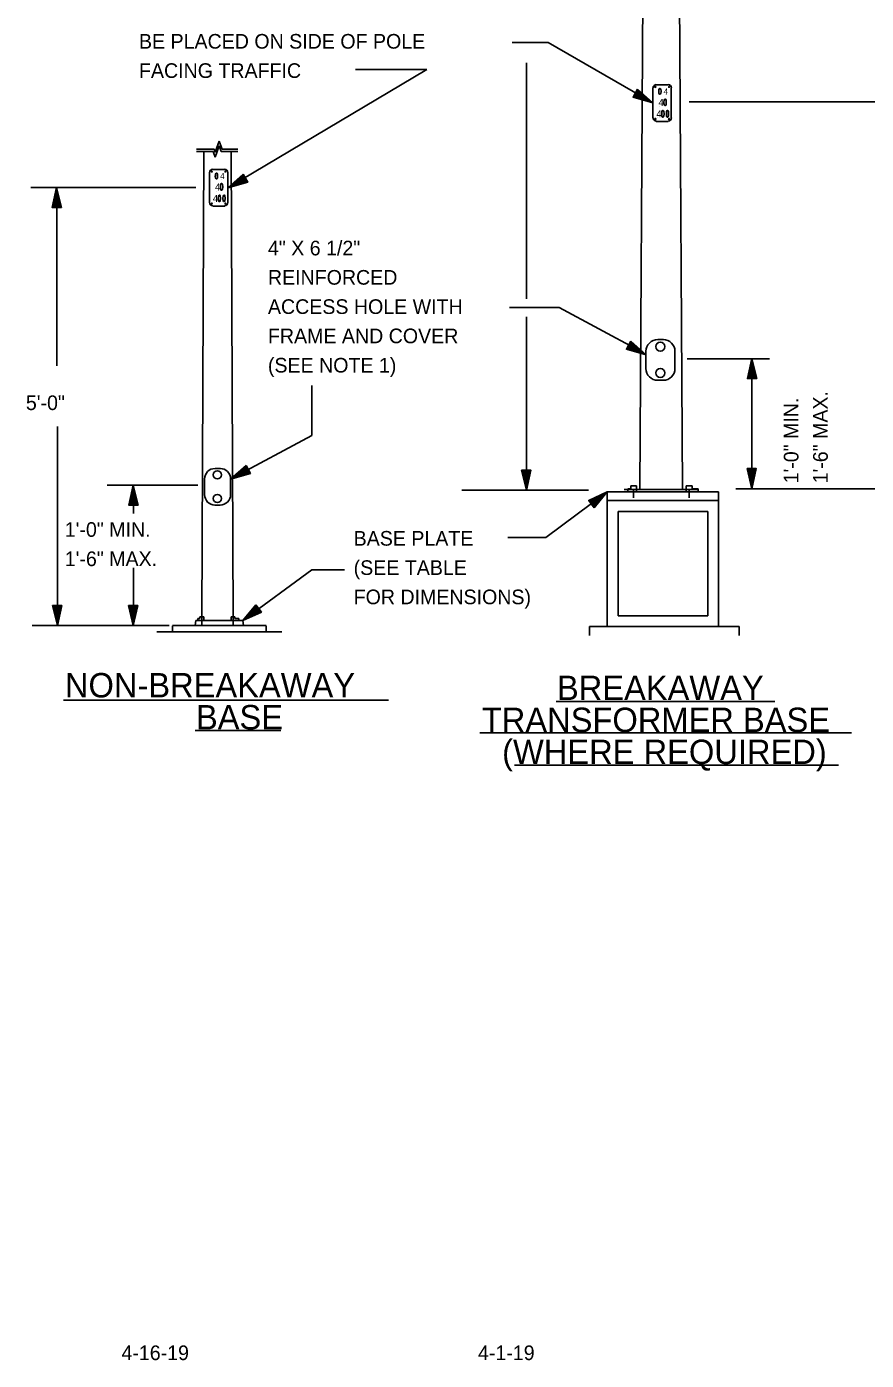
# Model space of a CAD drawing. Extents: x 9989.4 to 10000.1, y 10000.3 to 10010.3.
# Drawn here: x 9989.36 to 9992.8, y 10000.47 to 10005.94 of the extents above; entities that cross this region are included whole.
import ezdxf

# ---------------------------------------------------------------- set-up
doc = ezdxf.new("R2010")
doc.units = 0
for name, color, linetype in [('DETL-DIMS', 7, 'Continuous'), ('DETL-LINE', 7, 'Continuous'), ('DETL-NOTE', 7, 'Continuous'), ('DETL-TITL', 7, 'Continuous'), ('TTLB-TEXT', 7, 'Continuous'), ('V7_LEVEL_1', 7, 'Continuous')]:
    doc.layers.add(name, color=color, linetype=linetype)

# ---------------------------------------------------------------- blocks, each defined once
blk = doc.blocks.new('0')
at = {"layer": 'V7_LEVEL_1'}
blk.add_lwpolyline([(0.057, 0.015), (0.036, 0.022), (0.022, 0.042), (0.015, 0.079), (0.016, 0.102), (0.021, 0.135), (0.036, 0.158), (0.058, 0.165), (0.072, 0.165), (0.095, 0.158), (0.107, 0.137), (0.115, 0.104), (0.115, 0.079), (0.107, 0.043), (0.095, 0.024), (0.074, 0.015)], close=True, dxfattribs=at)

msp = doc.modelspace()

# ---------------------------------------------------------------- linework, layer by layer
at = {"layer": 'DETL-DIMS'}
for p, q in [((9991.5013, 10005.8695), (9991.354, 10005.8695)), ((9991.93, 10005.6225), (9991.5013, 10005.8695)), ((9990.1891, 10005.2749), (9991.0041, 10005.7598)), ((9991.0041, 10005.7598), (9990.7113, 10005.7598)), ((9991.412, 10005.7864), (9991.412, 10004.8195)), ((9992.078, 10005.627), (9993.3279, 10005.627)), ((9989.3818, 10005.2767), (9990.0576, 10005.2767)), ((9989.4881, 10005.2393), (9989.4881, 10004.5451)), ((9991.5463, 10004.7847), (9991.3426, 10004.7847)), ((9991.8716, 10004.61), (9991.5463, 10004.7847)), ((9991.412, 10004.7458), (9991.412, 10004.036)), ((9992.4072, 10004.574), (9992.0699, 10004.574)), ((9992.3356, 10004.575), (9992.3356, 10004.042)), ((9990.5324, 10004.2603), (9990.5324, 10004.465)), ((9989.4905, 10004.297), (9989.4905, 10003.4953)), ((9990.2072, 10004.0856), (9990.5324, 10004.2603)), ((9989.6945, 10004.0558), (9990.0665, 10004.0558)), ((9989.8018, 10004.0534), (9989.8018, 10003.9403)), ((9991.666, 10004.036), (9991.148, 10004.036)), ((9991.743, 10004.029), (9991.4919, 10003.8417)), ((9992.2692, 10004.042), (9993.3279, 10004.042)), ((9991.4919, 10003.8417), (9991.3353, 10003.8417)), ((9989.8018, 10003.5014), (9989.8018, 10003.7174)), ((9990.2501, 10003.5014), (9990.533, 10003.7095)), ((9990.533, 10003.7095), (9990.6661, 10003.7095)), ((9989.3866, 10003.4808), (9989.9481, 10003.4808))]:
    msp.add_line(p, q, dxfattribs=at)
for points in [[(9991.867, 10005.6785), (9991.93, 10005.6225), (9991.849, 10005.6455), (9991.867, 10005.6785)], [(9991.868, 10005.6755), (9991.923, 10005.6265), (9991.852, 10005.6465), (9991.868, 10005.6755)], [(9991.868, 10005.6725), (9991.916, 10005.6295), (9991.854, 10005.6475), (9991.868, 10005.6725)], [(9991.869, 10005.6705), (9991.909, 10005.6345), (9991.857, 10005.6485), (9991.869, 10005.6705)], [(9991.869, 10005.6675), (9991.902, 10005.6375), (9991.86, 10005.6495), (9991.869, 10005.6675)], [(9991.87, 10005.6645), (9991.895, 10005.6415), (9991.862, 10005.6505), (9991.87, 10005.6645)], [(9991.87, 10005.6615), (9991.889, 10005.6455), (9991.865, 10005.6515), (9991.87, 10005.6615)], [(9991.87, 10005.6585), (9991.882, 10005.6495), (9991.867, 10005.6525), (9991.87, 10005.6585)], [(9991.871, 10005.6565), (9991.875, 10005.6525), (9991.87, 10005.6545), (9991.871, 10005.6565)], [(9990.2521, 10005.3309), (9990.1891, 10005.2749), (9990.2701, 10005.2979), (9990.2521, 10005.3309)], [(9990.2511, 10005.3279), (9990.1961, 10005.2789), (9990.2671, 10005.2989), (9990.2511, 10005.3279)], [(9990.2511, 10005.3249), (9990.2031, 10005.2819), (9990.2651, 10005.2999), (9990.2511, 10005.3249)], [(9990.2501, 10005.3229), (9990.2101, 10005.2869), (9990.2621, 10005.3009), (9990.2501, 10005.3229)], [(9990.2501, 10005.3199), (9990.2171, 10005.2899), (9990.2591, 10005.3019), (9990.2501, 10005.3199)], [(9990.2491, 10005.3169), (9990.2241, 10005.2939), (9990.2571, 10005.3029), (9990.2491, 10005.3169)], [(9990.2491, 10005.3139), (9990.2301, 10005.2979), (9990.2541, 10005.3039), (9990.2491, 10005.3139)], [(9990.2491, 10005.3109), (9990.2371, 10005.3019), (9990.2521, 10005.3049), (9990.2491, 10005.3109)], [(9990.2481, 10005.3089), (9990.2441, 10005.3049), (9990.2491, 10005.3069), (9990.2481, 10005.3089)], [(9989.5069, 10005.1947), (9989.4869, 10005.2767), (9989.4689, 10005.1947), (9989.5069, 10005.1947)], [(9989.5039, 10005.1967), (9989.4869, 10005.2687), (9989.4709, 10005.1967), (9989.5039, 10005.1967)], [(9989.5019, 10005.1987), (9989.4869, 10005.2607), (9989.4729, 10005.1987), (9989.5019, 10005.1987)], [(9989.4999, 10005.1997), (9989.4869, 10005.2527), (9989.4759, 10005.1997), (9989.4999, 10005.1997)], [(9989.4969, 10005.2017), (9989.4869, 10005.2457), (9989.4779, 10005.2017), (9989.4969, 10005.2017)], [(9989.4949, 10005.2037), (9989.4869, 10005.2367), (9989.4799, 10005.2037), (9989.4949, 10005.2037)], [(9989.4929, 10005.2057), (9989.4869, 10005.2297), (9989.4819, 10005.2057), (9989.4929, 10005.2057)], [(9989.4909, 10005.2067), (9989.4879, 10005.2217), (9989.4839, 10005.2067), (9989.4909, 10005.2067)], [(9989.4889, 10005.2087), (9989.4879, 10005.2137), (9989.4869, 10005.2087), (9989.4889, 10005.2087)], [(9991.8393, 10004.6463), (9991.9023, 10004.5903), (9991.8213, 10004.6133), (9991.8393, 10004.6463)], [(9991.8403, 10004.6433), (9991.8953, 10004.5943), (9991.8243, 10004.6143), (9991.8403, 10004.6433)], [(9991.8403, 10004.6403), (9991.8883, 10004.5973), (9991.8263, 10004.6153), (9991.8403, 10004.6403)], [(9991.8413, 10004.6383), (9991.8813, 10004.6023), (9991.8293, 10004.6163), (9991.8413, 10004.6383)], [(9991.8413, 10004.6353), (9991.8743, 10004.6053), (9991.8323, 10004.6173), (9991.8413, 10004.6353)], [(9991.8423, 10004.6323), (9991.8673, 10004.6093), (9991.8343, 10004.6183), (9991.8423, 10004.6323)], [(9991.8423, 10004.6293), (9991.8613, 10004.6133), (9991.8373, 10004.6193), (9991.8423, 10004.6293)], [(9991.8423, 10004.6263), (9991.8543, 10004.6173), (9991.8393, 10004.6203), (9991.8423, 10004.6263)], [(9991.8433, 10004.6243), (9991.8473, 10004.6203), (9991.8423, 10004.6223), (9991.8433, 10004.6243)], [(9992.3556, 10004.493), (9992.3356, 10004.575), (9992.3176, 10004.493), (9992.3556, 10004.493)], [(9992.3526, 10004.495), (9992.3356, 10004.567), (9992.3196, 10004.495), (9992.3526, 10004.495)], [(9992.3506, 10004.497), (9992.3356, 10004.559), (9992.3216, 10004.497), (9992.3506, 10004.497)], [(9992.3486, 10004.498), (9992.3356, 10004.551), (9992.3246, 10004.498), (9992.3486, 10004.498)], [(9992.3456, 10004.5), (9992.3356, 10004.544), (9992.3266, 10004.5), (9992.3456, 10004.5)], [(9992.3436, 10004.502), (9992.3356, 10004.535), (9992.3286, 10004.502), (9992.3436, 10004.502)], [(9992.3416, 10004.504), (9992.3356, 10004.528), (9992.3306, 10004.504), (9992.3416, 10004.504)], [(9992.3396, 10004.505), (9992.3366, 10004.52), (9992.3326, 10004.505), (9992.3396, 10004.505)], [(9992.3376, 10004.507), (9992.3366, 10004.512), (9992.3356, 10004.507), (9992.3376, 10004.507)], [(9990.2632, 10004.1376), (9990.2002, 10004.0816), (9990.2812, 10004.1046), (9990.2632, 10004.1376)], [(9990.2622, 10004.1346), (9990.2072, 10004.0856), (9990.2782, 10004.1056), (9990.2622, 10004.1346)], [(9990.2622, 10004.1316), (9990.2142, 10004.0886), (9990.2762, 10004.1066), (9990.2622, 10004.1316)], [(9990.2612, 10004.1296), (9990.2212, 10004.0936), (9990.2732, 10004.1076), (9990.2612, 10004.1296)], [(9990.2612, 10004.1266), (9990.2282, 10004.0966), (9990.2702, 10004.1086), (9990.2612, 10004.1266)], [(9990.2602, 10004.1236), (9990.2352, 10004.1006), (9990.2682, 10004.1096), (9990.2602, 10004.1236)], [(9990.2602, 10004.1206), (9990.2412, 10004.1046), (9990.2652, 10004.1106), (9990.2602, 10004.1206)], [(9990.2602, 10004.1176), (9990.2482, 10004.1086), (9990.2632, 10004.1116), (9990.2602, 10004.1176)], [(9990.2592, 10004.1156), (9990.2552, 10004.1116), (9990.2602, 10004.1136), (9990.2592, 10004.1156)], [(9991.392, 10004.118), (9991.412, 10004.036), (9991.43, 10004.118), (9991.392, 10004.118)], [(9991.395, 10004.116), (9991.412, 10004.044), (9991.428, 10004.116), (9991.395, 10004.116)], [(9991.397, 10004.114), (9991.412, 10004.052), (9991.426, 10004.114), (9991.397, 10004.114)], [(9991.399, 10004.113), (9991.412, 10004.06), (9991.423, 10004.113), (9991.399, 10004.113)], [(9991.402, 10004.111), (9991.412, 10004.067), (9991.421, 10004.111), (9991.402, 10004.111)], [(9991.404, 10004.109), (9991.412, 10004.076), (9991.419, 10004.109), (9991.404, 10004.109)], [(9991.406, 10004.107), (9991.412, 10004.083), (9991.417, 10004.107), (9991.406, 10004.107)], [(9991.408, 10004.106), (9991.411, 10004.091), (9991.415, 10004.106), (9991.408, 10004.106)], [(9992.3156, 10004.124), (9992.3356, 10004.042), (9992.3536, 10004.124), (9992.3156, 10004.124)], [(9992.3186, 10004.122), (9992.3356, 10004.05), (9992.3516, 10004.122), (9992.3186, 10004.122)], [(9992.3206, 10004.12), (9992.3356, 10004.058), (9992.3496, 10004.12), (9992.3206, 10004.12)], [(9992.3226, 10004.119), (9992.3356, 10004.066), (9992.3466, 10004.119), (9992.3226, 10004.119)], [(9992.3256, 10004.117), (9992.3356, 10004.073), (9992.3446, 10004.117), (9992.3256, 10004.117)], [(9992.3276, 10004.115), (9992.3356, 10004.082), (9992.3426, 10004.115), (9992.3276, 10004.115)], [(9992.3296, 10004.113), (9992.3356, 10004.089), (9992.3406, 10004.113), (9992.3296, 10004.113)], [(9992.3316, 10004.112), (9992.3346, 10004.097), (9992.3386, 10004.112), (9992.3316, 10004.112)], [(9992.3336, 10004.11), (9992.3346, 10004.105), (9992.3356, 10004.11), (9992.3336, 10004.11)], [(9989.8214, 10003.9738), (9989.8014, 10004.0558), (9989.7834, 10003.9738), (9989.8214, 10003.9738)], [(9991.41, 10004.104), (9991.411, 10004.099), (9991.412, 10004.104), (9991.41, 10004.104)], [(9989.8184, 10003.9758), (9989.8014, 10004.0478), (9989.7854, 10003.9758), (9989.8184, 10003.9758)], [(9989.8164, 10003.9778), (9989.8014, 10004.0398), (9989.7874, 10003.9778), (9989.8164, 10003.9778)], [(9989.8144, 10003.9788), (9989.8014, 10004.0318), (9989.7904, 10003.9788), (9989.8144, 10003.9788)], [(9989.8114, 10003.9808), (9989.8014, 10004.0248), (9989.7924, 10003.9808), (9989.8114, 10003.9808)], [(9989.8094, 10003.9828), (9989.8014, 10004.0158), (9989.7944, 10003.9828), (9989.8094, 10003.9828)], [(9989.8074, 10003.9848), (9989.8014, 10004.0088), (9989.7964, 10003.9848), (9989.8074, 10003.9848)], [(9989.8054, 10003.9858), (9989.8024, 10004.0008), (9989.7984, 10003.9858), (9989.8054, 10003.9858)], [(9991.689, 10003.964), (9991.743, 10004.029), (9991.667, 10003.994), (9991.689, 10003.964)], [(9991.689, 10003.967), (9991.737, 10004.024), (9991.669, 10003.994), (9991.689, 10003.967)], [(9991.689, 10003.97), (9991.73, 10004.02), (9991.672, 10003.993), (9991.689, 10003.97)], [(9991.689, 10003.973), (9991.724, 10004.014), (9991.675, 10003.992), (9991.689, 10003.973)], [(9991.689, 10003.976), (9991.718, 10004.01), (9991.678, 10003.991), (9991.689, 10003.976)], [(9991.689, 10003.978), (9991.712, 10004.005), (9991.68, 10003.991), (9991.689, 10003.978)], [(9991.69, 10003.981), (9991.705, 10004), (9991.683, 10003.99), (9991.69, 10003.981)], [(9989.8034, 10003.9878), (9989.8024, 10003.9928), (9989.8014, 10003.9878), (9989.8034, 10003.9878)], [(9991.69, 10003.984), (9991.699, 10003.995), (9991.686, 10003.989), (9991.69, 10003.984)], [(9991.69, 10003.987), (9991.693, 10003.991), (9991.688, 10003.989), (9991.69, 10003.987)], [(9989.4705, 10003.5628), (9989.4905, 10003.4808), (9989.5085, 10003.5628), (9989.4705, 10003.5628)], [(9989.4735, 10003.5608), (9989.4905, 10003.4888), (9989.5065, 10003.5608), (9989.4735, 10003.5608)], [(9989.4755, 10003.5588), (9989.4905, 10003.4968), (9989.5045, 10003.5588), (9989.4755, 10003.5588)], [(9989.7814, 10003.5628), (9989.8014, 10003.4808), (9989.8194, 10003.5628), (9989.7814, 10003.5628)], [(9989.7844, 10003.5608), (9989.8014, 10003.4888), (9989.8174, 10003.5608), (9989.7844, 10003.5608)], [(9989.7864, 10003.5588), (9989.8014, 10003.4968), (9989.8154, 10003.5588), (9989.7864, 10003.5588)], [(9990.3041, 10003.5664), (9990.2501, 10003.5014), (9990.3261, 10003.5364), (9990.3041, 10003.5664)], [(9990.3041, 10003.5634), (9990.2561, 10003.5064), (9990.3241, 10003.5364), (9990.3041, 10003.5634)], [(9990.3041, 10003.5604), (9990.2631, 10003.5104), (9990.3211, 10003.5374), (9990.3041, 10003.5604)], [(9989.4775, 10003.5578), (9989.4905, 10003.5048), (9989.5015, 10003.5578), (9989.4775, 10003.5578)], [(9989.4805, 10003.5558), (9989.4905, 10003.5118), (9989.4995, 10003.5558), (9989.4805, 10003.5558)], [(9989.4825, 10003.5538), (9989.4905, 10003.5208), (9989.4975, 10003.5538), (9989.4825, 10003.5538)], [(9989.4845, 10003.5518), (9989.4905, 10003.5278), (9989.4955, 10003.5518), (9989.4845, 10003.5518)], [(9989.4865, 10003.5508), (9989.4895, 10003.5358), (9989.4935, 10003.5508), (9989.4865, 10003.5508)], [(9989.4885, 10003.5488), (9989.4895, 10003.5438), (9989.4905, 10003.5488), (9989.4885, 10003.5488)], [(9989.7884, 10003.5578), (9989.8014, 10003.5048), (9989.8124, 10003.5578), (9989.7884, 10003.5578)], [(9989.7914, 10003.5558), (9989.8014, 10003.5118), (9989.8104, 10003.5558), (9989.7914, 10003.5558)], [(9989.7934, 10003.5538), (9989.8014, 10003.5208), (9989.8084, 10003.5538), (9989.7934, 10003.5538)], [(9989.7954, 10003.5518), (9989.8014, 10003.5278), (9989.8064, 10003.5518), (9989.7954, 10003.5518)], [(9989.7974, 10003.5508), (9989.8004, 10003.5358), (9989.8044, 10003.5508), (9989.7974, 10003.5508)], [(9989.7994, 10003.5488), (9989.8004, 10003.5438), (9989.8014, 10003.5488), (9989.7994, 10003.5488)], [(9990.3041, 10003.5574), (9990.2691, 10003.5164), (9990.3181, 10003.5384), (9990.3041, 10003.5574)], [(9990.3041, 10003.5544), (9990.2751, 10003.5204), (9990.3151, 10003.5394), (9990.3041, 10003.5544)], [(9990.3041, 10003.5524), (9990.2811, 10003.5254), (9990.3131, 10003.5394), (9990.3041, 10003.5524)], [(9990.3031, 10003.5494), (9990.2881, 10003.5304), (9990.3101, 10003.5404), (9990.3031, 10003.5494)], [(9990.3031, 10003.5464), (9990.2941, 10003.5354), (9990.3071, 10003.5414), (9990.3031, 10003.5464)], [(9990.3031, 10003.5434), (9990.3001, 10003.5394), (9990.3051, 10003.5414), (9990.3031, 10003.5434)]]:
    msp.add_lwpolyline(points, dxfattribs=at)
at = {"layer": 'DETL-LINE'}
for p, q in [((9991.916, 10010.078), (9991.876, 10004.038)), ((9992.012, 10010.078), (9992.052, 10004.038)), ((9991.943, 10005.697), (9991.992, 10005.697)), ((9991.93, 10005.561), (9991.93, 10005.684)), ((9991.98, 10005.656), (9991.98, 10005.656)), ((9992.005, 10005.684), (9992.005, 10005.561)), ((9991.959, 10005.609), (9991.959, 10005.609)), ((9991.992, 10005.547), (9991.943, 10005.547)), ((9991.949, 10005.562), (9991.949, 10005.562)), ((9990.0601, 10005.4336), (9990.1325, 10005.4336)), ((9990.0601, 10005.4236), (9990.1287, 10005.4236)), ((9990.0821, 10003.5094), (9990.09, 10005.4236)), ((9990.1287, 10005.4236), (9990.1369, 10005.401)), ((9990.1325, 10005.4336), (9990.1372, 10005.4207)), ((9990.1369, 10005.401), (9990.1534, 10005.4461)), ((9990.1372, 10005.4207), (9990.1535, 10005.4654)), ((9990.1534, 10005.4461), (9990.1616, 10005.4236)), ((9990.1535, 10005.4654), (9990.1651, 10005.4336)), ((9990.1616, 10005.4236), (9990.2302, 10005.4236)), ((9990.1651, 10005.4336), (9990.2302, 10005.4336)), ((9990.2101, 10003.5094), (9990.2021, 10005.4236)), ((9990.1141, 10005.2134), (9990.1141, 10005.3364)), ((9990.1271, 10005.3494), (9990.1761, 10005.3494)), ((9990.1641, 10005.3084), (9990.1641, 10005.3084)), ((9990.1891, 10005.3364), (9990.1891, 10005.2134)), ((9990.1431, 10005.2614), (9990.1431, 10005.2614)), ((9990.1761, 10005.1994), (9990.1271, 10005.1994)), ((9990.1331, 10005.2144), (9990.1331, 10005.2144)), ((9991.9498, 10004.6528), (9991.9738, 10004.6528)), ((9991.9018, 10004.5328), (9991.9018, 10004.6048)), ((9992.02, 10004.606), (9992.02, 10004.534)), ((9991.9018, 10004.5341), (9991.9018, 10004.5328)), ((9991.972, 10004.486), (9991.948, 10004.486)), ((9990.1366, 10004.1248), (9990.1582, 10004.1248)), ((9990.0934, 10004.0168), (9990.0934, 10004.0816)), ((9990.1998, 10004.0826), (9990.1998, 10004.0178)), ((9991.839, 10004.053), (9991.851, 10004.053)), ((9991.839, 10004.041), (9991.839, 10004.053)), ((9991.851, 10004.053), (9991.863, 10004.053)), ((9991.851, 10004.053), (9991.851, 10004.053)), ((9991.863, 10004.053), (9991.863, 10004.029)), ((9992.067, 10004.053), (9992.067, 10004.029)), ((9992.079, 10004.053), (9992.067, 10004.053)), ((9992.079, 10004.053), (9992.091, 10004.053)), ((9992.091, 10004.053), (9992.091, 10004.041)), ((9990.0934, 10004.0179), (9990.0934, 10004.0168)), ((9991.743, 10004.029), (9992.013, 10004.029)), ((9991.743, 10003.477), (9991.743, 10004.029)), ((9991.812, 10004.038), (9992.116, 10004.038)), ((9991.827, 10004.041), (9991.827, 10004.029)), ((9991.839, 10004.041), (9991.827, 10004.041)), ((9991.839, 10004.041), (9991.839, 10004.041)), ((9991.851, 10004.041), (9991.851, 10004.005)), ((9992.013, 10004.029), (9992.199, 10004.029)), ((9992.079, 10004.041), (9992.079, 10004.005)), ((9992.091, 10004.041), (9992.115, 10004.041)), ((9992.115, 10004.041), (9992.115, 10004.029)), ((9992.199, 10003.477), (9992.199, 10004.029)), ((9990.1566, 10003.9746), (9990.135, 10003.9746)), ((9991.743, 10003.993), (9992.013, 10003.993)), ((9991.7874, 10003.5214), (9991.7874, 10003.9486)), ((9991.7874, 10003.9486), (9992.013, 10003.9486)), ((9992.013, 10003.993), (9992.199, 10003.993)), ((9992.013, 10003.9486), (9992.1546, 10003.9486)), ((9992.1546, 10003.5214), (9992.1546, 10003.9486)), ((9990.0661, 10003.5094), (9990.0661, 10003.5014)), ((9990.0741, 10003.5094), (9990.0661, 10003.5094)), ((9990.0741, 10003.5174), (9990.0821, 10003.5174)), ((9990.0741, 10003.5094), (9990.0741, 10003.5174)), ((9990.0821, 10003.5174), (9990.0901, 10003.5174)), ((9990.0821, 10003.5094), (9990.0821, 10003.4854)), ((9990.0901, 10003.5174), (9990.0901, 10003.5014)), ((9990.2021, 10003.5174), (9990.2021, 10003.5014)), ((9990.2101, 10003.5174), (9990.2021, 10003.5174)), ((9990.2101, 10003.5174), (9990.2181, 10003.5174)), ((9990.2101, 10003.5094), (9990.2101, 10003.4854)), ((9990.2181, 10003.5174), (9990.2181, 10003.5094)), ((9990.2181, 10003.5094), (9990.2341, 10003.5094)), ((9990.2341, 10003.5094), (9990.2341, 10003.5014)), ((9991.7874, 10003.5214), (9992.013, 10003.5214)), ((9992.013, 10003.5214), (9992.1546, 10003.5214)), ((9989.8975, 10003.4554), (9990.4095, 10003.4554)), ((9989.9615, 10003.4808), (9990.3455, 10003.4808)), ((9989.9615, 10003.4794), (9989.9615, 10003.4554)), ((9990.0554, 10003.4808), (9990.0581, 10003.5014)), ((9990.0581, 10003.5014), (9990.2501, 10003.5014)), ((9990.2501, 10003.5014), (9990.2536, 10003.4808)), ((9990.3455, 10003.4794), (9990.3455, 10003.4554)), ((9991.671, 10003.477), (9991.671, 10003.441)), ((9991.671, 10003.477), (9992.013, 10003.477)), ((9992.013, 10003.477), (9992.283, 10003.477)), ((9992.283, 10003.477), (9992.283, 10003.441))]:
    msp.add_line(p, q, dxfattribs=at)
for centre, radius in [((9991.9402, 10005.6882), 0.00234), ((9991.9964, 10005.6882), 0.00234), ((9991.9402, 10005.557), 0.00234), ((9991.9964, 10005.557), 0.00234), ((9990.1231, 10005.3413), 0.00234), ((9990.1794, 10005.3413), 0.00234), ((9990.1231, 10005.2101), 0.00234), ((9990.1794, 10005.2101), 0.00234), ((9991.9602, 10004.624), 0.0186), ((9991.9602, 10004.5162), 0.0186), ((9990.1459, 10004.0989), 0.0168), ((9990.1459, 10004.0018), 0.0168)]:
    msp.add_circle(centre, radius, dxfattribs=at)
for centre, radius, start, end in [((9991.9441, 10005.6843), 0.0133, 90, 180), ((9991.9926, 10005.6843), 0.0133, 0, 90), ((9991.9441, 10005.5609), 0.0133, 180, 270), ((9991.9926, 10005.5609), 0.0133, 270, 0), ((9990.127, 10005.3375), 0.0133, 90, 180), ((9990.1755, 10005.3375), 0.0133, 0, 90), ((9990.127, 10005.214), 0.0133, 180, 270), ((9990.1755, 10005.214), 0.0133, 270, 0), ((9991.9498, 10004.6048), 0.048, 90, 180), ((9991.9724, 10004.6048), 0.048, 0, 90), ((9991.9498, 10004.5341), 0.048, 180, 270), ((9991.9724, 10004.5341), 0.048, 270, 0), ((9990.1366, 10004.0816), 0.0432, 90, 180), ((9990.157, 10004.0816), 0.0432, 0, 90), ((9990.1366, 10004.0179), 0.0432, 180, 270), ((9990.157, 10004.0179), 0.0432, 270, 0)]:
    msp.add_arc(centre, radius, start, end, dxfattribs=at)
at = {"layer": 'DETL-TITL'}
for p, q in [((9989.515, 10003.175), (9990.8469, 10003.175)), ((9991.5343, 10003.1702), (9992.4302, 10003.1702)), ((9990.0553, 10003.0517), (9990.4061, 10003.0517)), ((9991.2214, 10003.0422), (9992.743, 10003.0422)), ((9991.3636, 10002.9095), (9992.6909, 10002.9095))]:
    msp.add_line(p, q, dxfattribs=at)

# ---------------------------------------------------------------- block references
at = {"layer": 'DETL-LINE'}
for p, xscale, yscale in [((9991.953, 10005.656), 0.09170249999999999, 0.15327), ((9991.974, 10005.609), 0.091875, 0.178816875), ((9991.965, 10005.562), 0.091875, 0.178816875), ((9991.984, 10005.562), 0.091875, 0.178816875), ((9990.1361, 10005.3094), 0.09170249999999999, 0.15327), ((9990.1571, 10005.2624), 0.091875, 0.178816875), ((9990.1481, 10005.2154), 0.091875, 0.178816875), ((9990.1671, 10005.2154), 0.091875, 0.178816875)]:
    msp.add_blockref('0', p, dxfattribs=dict(at, xscale=xscale, yscale=yscale))

# ---------------------------------------------------------------- texts
for height, p in [(0.0293, (9991.953, 10005.61)), (0.0251, (9991.974, 10005.657)), (0.0293, (9991.944, 10005.563)), (0.0251, (9990.1571, 10005.3104)), (0.0293, (9990.1361, 10005.2634)), (0.0293, (9990.1271, 10005.2164))]:
    msp.add_text('4', height=height, dxfattribs=at).set_placement(p)
at = {"layer": 'DETL-NOTE'}
for s, p in [('BE PLACED ON SIDE OF POLE ', (9989.8248, 10005.845)), ('FACING TRAFFIC', (9989.8248, 10005.725)), ('4" X 6 1/2"', (9990.353, 10004.9979)), ('REINFORCED', (9990.353, 10004.8779)), ('ACCESS HOLE WITH', (9990.353, 10004.7579)), ('FRAME AND COVER', (9990.353, 10004.6379)), ('(SEE NOTE 1)', (9990.353, 10004.5179)), ('5\'-0"', (9989.3615, 10004.3641)), ('1\'-0" MIN.', (9989.5208, 10003.8447)), ('BASE PLATE ', (9990.7042, 10003.8085)), ('1\'-6" MAX.', (9989.5208, 10003.7247)), ('(SEE TABLE ', (9990.7042, 10003.6885)), ('FOR DIMENSIONS)', (9990.7042, 10003.5685))]:
    msp.add_text(s, height=0.06, dxfattribs=at).set_placement(p)
for s, p in [('1\'-6" MAX.', (9992.6464, 10004.0637)), ('1\'-0" MIN.', (9992.5264, 10004.0637))]:
    msp.add_text(s, height=0.06, rotation=90, dxfattribs=at).set_placement(p)
at = {"layer": 'DETL-TITL'}
for s, height, p in [('NON-BREAKAWAY ', 0.100002, (9989.5213, 10003.1867)), ('BREAKAWAY ', 0.1, (9991.537, 10003.1759)), ('BASE', 0.1, (9990.0581, 10003.0556)), ('TRANSFORMER BASE ', 0.100002, (9991.2293, 10003.0447)), ('(WHERE REQUIRED)', 0.100002, (9991.3124, 10002.9136))]:
    msp.add_text(s, height=height, dxfattribs=at).set_placement(p)
at = {"layer": 'TTLB-TEXT'}
for s, p in [('4-16-19', (9989.753, 10000.4713)), ('4-1-19', (9991.2136, 10000.4713))]:
    msp.add_text(s, height=0.06, dxfattribs=at).set_placement(p)

doc.saveas('drawing.dxf')
